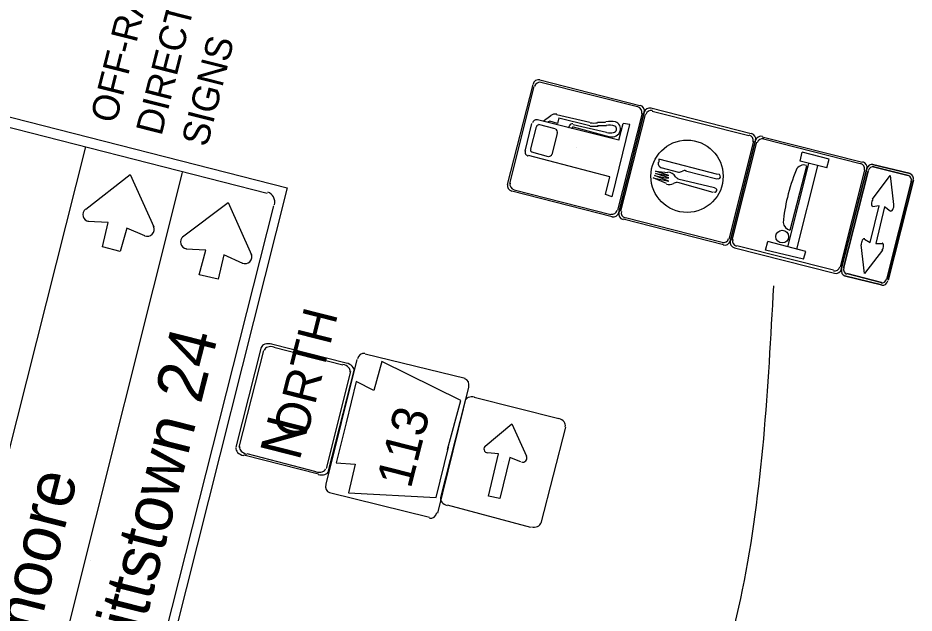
# Model space of a CAD drawing. Extents: x 644898 to 648326, y 298294 to 300670.
# Drawn here: x 647909.2 to 648009.9, y 300525.8 to 300592.6 of the extents above; entities that cross this region are included whole.
import ezdxf

# ---------------------------------------------------------------- set-up
doc = ezdxf.new("R2010")
doc.units = 0
doc.layers.add('2', color=7, linetype='Continuous')

msp = doc.modelspace()

# ---------------------------------------------------------------- linework, layer by layer
at = {"layer": '2'}
for p, q in [((647964.2, 300573.87), (647967.07, 300585.12)), ((647964.45, 300573.99), (647967.2, 300584.87)), ((647967.82, 300585.62), (647979.07, 300582.74)), ((647967.95, 300585.37), (647978.82, 300582.62)), ((647905.7, 300582.12), (647939.45, 300573.49)), ((647979.32, 300581.87), (647976.57, 300570.99)), ((647979.57, 300581.99), (647976.7, 300570.74)), ((647976.7, 300570.74), (647979.57, 300581.99)), ((647980.32, 300582.49), (647991.57, 300579.62)), ((647980.45, 300582.12), (647991.32, 300579.37)), ((647966.2, 300577.62), (647966.95, 300580.74)), ((647976.7, 300578.87), (647967.57, 300581.12)), ((647968.2, 300580.99), (647969.07, 300581.62)), ((647968.95, 300580.99), (647968.7, 300580.87)), ((647969.82, 300580.74), (647968.95, 300580.99)), ((647969.7, 300581.74), (647973.45, 300580.87)), ((647969.95, 300581.37), (647969.82, 300580.74)), ((647969.95, 300581.37), (647973.45, 300580.49)), ((647974.32, 300580.87), (647975.2, 300580.87)), ((647976.7, 300578.87), (647977.2, 300580.74)), ((647976.95, 300570.87), (647979.7, 300581.74)), ((647977.95, 300580.62), (647977.2, 300580.74)), ((647937.2, 300572.87), (647907.32, 300580.49)), ((647966.82, 300577.87), (647967.45, 300580.37)), ((647969.57, 300580.12), (647967.7, 300580.62)), ((647971.07, 300580.24), (647971.2, 300580.49)), ((647971.45, 300580.12), (647971.45, 300580.24)), ((647971.57, 300580.62), (647975.32, 300579.74)), ((647971.57, 300580.37), (647975.7, 300579.24)), ((647974.32, 300580.49), (647975.32, 300580.49)), ((647975.95, 300572.49), (647977.95, 300580.62)), ((647969.2, 300577.24), (647969.82, 300579.62)), ((647991.82, 300578.74), (647989.07, 300567.74)), ((647992.07, 300578.87), (647989.2, 300567.49)), ((647989.2, 300567.49), (647992.07, 300578.87)), ((647992.82, 300579.24), (648004.07, 300576.37)), ((647992.95, 300578.99), (648003.82, 300576.24)), ((647898.32, 300504.87), (647916.82, 300578.12)), ((647971.95, 300577.99), (647971.95, 300577.99)), ((647989.45, 300567.62), (647992.2, 300578.62)), ((647975.7, 300574.74), (647966.57, 300577.12)), ((647968.82, 300576.99), (647966.95, 300577.49)), ((647987.82, 300574.99), (647981.2, 300576.74)), ((647981.2, 300576.74), (647981.2, 300576.37)), ((647997.07, 300576.49), (647997.32, 300577.49)), ((648000.32, 300576.74), (647997.32, 300577.49)), ((648000.07, 300575.74), (648000.32, 300576.74)), ((647983.45, 300575.24), (647981.45, 300575.74)), ((647995.7, 300566.87), (647998.07, 300576.24)), ((647995.95, 300568.74), (647997.82, 300575.99)), ((647996.7, 300566.62), (647999.07, 300575.99)), ((648000.07, 300575.74), (647997.07, 300576.49)), ((648005.2, 300576.12), (648009.45, 300575.12)), ((648009.45, 300575.12), (648005.2, 300576.12)), ((648005.32, 300575.87), (648009.2, 300574.87)), ((648009.2, 300574.87), (648005.32, 300575.87)), ((647909.32, 300502.12), (647927.7, 300575.24)), ((647916.82, 300571.12), (647921.82, 300574.99)), ((647921.82, 300574.99), (647924.45, 300569.12)), ((647975.2, 300572.74), (647975.7, 300574.74)), ((647982.32, 300574.24), (647980.7, 300574.87)), ((647980.7, 300574.87), (647981.95, 300574.62)), ((647980.82, 300575.37), (647982.2, 300575.24)), ((647982.32, 300574.87), (647980.82, 300575.37)), ((647982.32, 300574.62), (647980.82, 300575.12)), ((647980.82, 300575.12), (647982.32, 300574.87)), ((647987.7, 300574.49), (647984.2, 300575.37)), ((647984.45, 300574.74), (647984.45, 300574.74)), ((648004.32, 300575.49), (648001.57, 300564.62)), ((648004.57, 300575.62), (648001.7, 300564.37)), ((648001.7, 300564.37), (648004.57, 300575.62)), ((648004.57, 300575.62), (648001.7, 300564.37)), ((648001.95, 300564.49), (648004.7, 300575.37)), ((648004.7, 300575.37), (648001.95, 300564.49)), ((648005.2, 300572.24), (648007.2, 300574.87)), ((648007.2, 300574.87), (648007.57, 300571.62)), ((647982.07, 300573.99), (647980.57, 300574.62)), ((647980.57, 300574.62), (647982.32, 300574.24)), ((647981.95, 300574.62), (647982.32, 300574.62)), ((647987.45, 300573.49), (647983.32, 300574.49)), ((647987.32, 300572.99), (647983.32, 300574.12)), ((648009.57, 300574.24), (648006.82, 300563.24)), ((648006.82, 300563.24), (648009.57, 300574.24)), ((648009.82, 300574.37), (648006.95, 300563.12)), ((648006.95, 300563.12), (648009.82, 300574.37)), ((647939.45, 300573.49), (647920.45, 300498.24)), ((647975.95, 300570.24), (647964.7, 300573.12)), ((647975.82, 300570.49), (647964.95, 300573.24)), ((647975.95, 300572.49), (647975.2, 300572.74)), ((647927.7, 300567.99), (647932.82, 300571.87)), ((647932.82, 300571.87), (647935.45, 300565.99)), ((647919.95, 300500.49), (647937.95, 300571.49)), ((647996.95, 300571.62), (647996.95, 300571.62)), ((648004.95, 300567.37), (648005.95, 300571.49)), ((648004.95, 300567.37), (648005.95, 300571.49)), ((648005.95, 300571.49), (648005.2, 300571.37)), ((648006.57, 300571.37), (648005.57, 300567.24)), ((648006.57, 300571.37), (648005.57, 300567.24)), ((648007.2, 300570.87), (648006.57, 300571.37)), ((647919.32, 300569.62), (647917.07, 300569.74)), ((647988.45, 300567.12), (647977.2, 300569.99)), ((647988.32, 300567.37), (647977.45, 300570.12)), ((647918.7, 300566.87), (647919.32, 300569.62)), ((647921.45, 300568.99), (647920.7, 300566.37)), ((647923.45, 300568.12), (647921.45, 300568.99)), ((648005.7, 300569.37), (648005.7, 300569.37)), ((648005.7, 300569.37), (648005.7, 300569.37)), ((648005.7, 300569.37), (648005.7, 300569.37)), ((648005.7, 300569.37), (648005.7, 300569.37)), ((648004.32, 300567.74), (648004.95, 300567.37)), ((647920.7, 300566.37), (647918.7, 300566.87)), ((648000.95, 300563.87), (647989.7, 300566.74)), ((648000.82, 300564.24), (647989.95, 300566.99)), ((647993.2, 300566.49), (647993.45, 300567.49)), ((647997.7, 300566.37), (647993.45, 300567.49)), ((648004.32, 300563.87), (648003.95, 300567.12)), ((648005.57, 300567.24), (648006.32, 300567.24)), ((647930.32, 300566.49), (647928.07, 300566.62)), ((647929.57, 300563.74), (647930.32, 300566.49)), ((647932.32, 300565.99), (647931.7, 300563.24)), ((647934.45, 300564.99), (647932.32, 300565.99)), ((647997.45, 300565.49), (647993.2, 300566.49)), ((647997.45, 300565.49), (647997.7, 300566.37)), ((648006.32, 300566.49), (648004.32, 300563.87)), ((647931.7, 300563.24), (647929.57, 300563.74)), ((648006.2, 300562.87), (648002.32, 300563.87)), ((648002.32, 300563.87), (648006.2, 300562.87)), ((648006.2, 300562.62), (648002.07, 300563.62)), ((648002.07, 300563.62), (648006.2, 300562.62)), ((647933.7, 300544.37), (647936.57, 300555.62)), ((647937.7, 300555.99), (647946.07, 300553.87)), ((647937.95, 300555.62), (647945.7, 300553.62)), ((647934.07, 300544.37), (647936.82, 300555.24)), ((647948.2, 300554.87), (647959.45, 300552.12)), ((647943.82, 300540.24), (647947.32, 300554.24)), ((647950.07, 300553.99), (647949.2, 300550.74)), ((647958.95, 300549.62), (647950.07, 300553.99)), ((647946.57, 300552.87), (647943.82, 300541.99)), ((647946.95, 300552.99), (647944.07, 300541.74)), ((647947.2, 300551.74), (647946.07, 300547.12)), ((647949.2, 300550.74), (647947.2, 300551.74)), ((647959.82, 300551.12), (647956.32, 300536.99)), ((647957.45, 300544.12), (647958.95, 300549.62)), ((647960.45, 300549.99), (647969.95, 300547.62)), ((647960.45, 300549.99), (647969.95, 300547.62)), ((647960.45, 300549.99), (647969.95, 300547.62)), ((647940.32, 300548.62), (647940.32, 300548.62)), ((647956.7, 300538.74), (647959.45, 300549.49)), ((647956.7, 300538.74), (647959.45, 300549.49)), ((647956.7, 300538.74), (647959.45, 300549.49)), ((647946.07, 300547.12), (647944.95, 300542.62)), ((647961.7, 300544.49), (647964.7, 300546.99)), ((647964.7, 300546.99), (647966.32, 300543.37)), ((647970.7, 300546.62), (647967.95, 300535.87)), ((647970.7, 300546.62), (647967.95, 300535.87)), ((647970.7, 300546.62), (647967.95, 300535.87)), ((647942.95, 300541.37), (647934.57, 300543.49)), ((647942.7, 300541.62), (647934.95, 300543.62)), ((647956.2, 300538.74), (647957.57, 300544.37)), ((647963.2, 300543.62), (647961.95, 300543.74)), ((647962.07, 300538.87), (647963.2, 300543.62)), ((647944.95, 300542.62), (647947.07, 300542.49)), ((647947.07, 300542.49), (647946.32, 300539.24)), ((647964.45, 300543.24), (647963.32, 300538.62)), ((647963.7, 300542.74), (647963.7, 300542.74)), ((647963.7, 300542.74), (647963.7, 300542.74)), ((647963.7, 300542.74), (647963.7, 300542.74)), ((647965.7, 300542.74), (647964.45, 300543.24)), ((647955.45, 300536.49), (647944.2, 300539.24)), ((647946.32, 300539.24), (647956.2, 300538.74)), ((647963.32, 300538.62), (647962.07, 300538.87)), ((647966.82, 300535.37), (647957.45, 300537.87)), ((647966.82, 300535.37), (647957.45, 300537.87)), ((647966.82, 300535.37), (647957.45, 300537.87)), ((647955.45, 300536.49), (647955.45, 300536.49)), ((647917.45, 300534.49), (647917.45, 300534.49)), ((647917.45, 300534.49), (647917.45, 300534.49)), ((647917.32, 300531.62), (647917.32, 300531.62)), ((647928.2, 300528.87), (647928.2, 300528.87)), ((647928.2, 300528.87), (647928.2, 300528.87))]:
    msp.add_line(p, q, dxfattribs=at)
for centre, radius in [((647984.37, 300574.8), 4.06), ((647995.06, 300568.03), 0.717)]:
    msp.add_circle(centre, radius, dxfattribs=at)
for centre, radius, start, end in [((647967.69, 300584.99), 0.645, 75.7754, 165.7754), ((647967.83, 300584.76), 0.597, 75.7754, 165.7754), ((647978.94, 300582.14), 0.645, 345.7754, 75.7754), ((647969.59, 300580.79), 0.991, 81.3158, 122.9841), ((647978.71, 300582), 0.597, 345.7754, 75.7754), ((647980.19, 300581.82), 0.645, 75.7754, 165.7754), ((647980.33, 300581.59), 0.597, 75.7754, 165.7754), ((647967.47, 300580.67), 0.486, 83.6778, 164.7031), ((647973.9, 300583.76), 2.98, 262.3862, 278.0519), ((647975.78, 300578.28), 2.68, 78.1727, 101.1253), ((647976.06, 300580.11), 0.84, 344.9893, 71.1198), ((647967.71, 300580.3), 0.274, 92.8615, 169.1523), ((647969.41, 300579.75), 0.392, 341.4902, 59.3145), ((647971.46, 300580.37), 0.318, 75.201, 153.6335), ((647971.54, 300580.24), 0.0771, 64.9719, 167.615), ((647973.9, 300583.76), 3.35, 262.3862, 278.0519), ((647975.67, 300578.96), 1.59, 68.02, 103.4387), ((647975.96, 300580.18), 0.953, 254.9902, 342.4176), ((647976.07, 300580.11), 0.381, 275.7441, 58.872), ((647975.71, 300581.2), 1.53, 256.8807, 285.2561), ((647991.22, 300578.83), 0.597, 345.7754, 75.7754), ((647991.45, 300578.97), 0.645, 345.7754, 75.7754), ((647992.7, 300578.65), 0.645, 75.7754, 165.7754), ((647992.84, 300578.42), 0.597, 75.7754, 165.7754), ((647967.03, 300577.75), 0.249, 154.0614, 244.0323), ((647966.59, 300577.5), 0.415, 157.4008, 262.3628), ((647968.88, 300577.35), 0.314, 262.0164, 342.4308), ((647981.63, 300576.25), 0.507, 165.7754, 255.7754), ((647997.47, 300575.18), 0.888, 69.9409, 158.7047), ((648003.72, 300575.66), 0.597, 345.7754, 75.7754), ((648003.95, 300575.8), 0.645, 345.7754, 75.7754), ((647982.21, 300574.25), 0.996, 30.4773, 89.3124), ((647983.51, 300575.01), 0.504, 210.7055, 255.4294), ((647983.44, 300576.11), 0.835, 266.9017, 299.9124), ((647984.1, 300575.01), 0.443, 68.9162, 122.8856), ((647987.86, 300574.78), 0.261, 247.2807, 84.2701), ((648013.8, 300568.22), 18.64, 157.0049, 166.9537), ((647964.84, 300573.74), 0.645, 165.7754, 255.7754), ((647965.07, 300573.88), 0.597, 165.7754, 255.7754), ((647982.41, 300574.73), 0.869, 247.3155, 299.7154), ((647983.18, 300573.5), 0.593, 81.6072, 125.4072), ((647987.48, 300573.25), 0.234, 244.4009, 87.1499), ((648017.53, 300567.22), 22.5, 166.6162, 173.9535), ((647917.23, 300570.5), 0.745, 125.638, 266.3035), ((647975.95, 300571.12), 0.597, 255.7754, 345.7754), ((647976.09, 300570.88), 0.645, 255.7754, 345.7754), ((647977.34, 300570.57), 0.645, 165.7754, 255.7754), ((647977.57, 300570.71), 0.597, 165.7754, 255.7754), ((647923.76, 300568.8), 0.745, 244.0264, 27.9331), ((647996.19, 300569.75), 1.04, 188.6173, 255.6836), ((647928.2, 300567.43), 0.745, 125.638, 266.3035), ((647988.46, 300567.95), 0.597, 255.7754, 345.7754), ((647990.08, 300567.54), 0.597, 165.7754, 255.7754), ((647988.6, 300567.71), 0.645, 255.7754, 345.7754), ((647989.85, 300567.4), 0.645, 165.7754, 255.7754), ((647934.73, 300565.73), 0.745, 244.0264, 27.9331), ((648000.96, 300564.78), 0.597, 255.7754, 345.7754), ((648001.1, 300564.54), 0.645, 255.7754, 345.7754), ((647962, 300544.19), 0.45, 126.1169, 265.3481), ((647965.93, 300543.16), 0.45, 247.2918, 24.1455)]:
    msp.add_arc(centre, radius, start, end, dxfattribs=at)
for centre, major_axis, ratio, start_param, end_param in [((648005.1, 300575.51), (-0.158, -0.625), 0.833333, 3.141593, 4.712389), ((648005.1, 300575.51), (0.158, 0.625), 0.833333, 0, 1.570796), ((648005.21, 300575.28), (-0.147, -0.578), 0.833333, 3.141593, 4.712389), ((648005.21, 300575.28), (0.147, 0.578), 0.833333, 0, 1.570796), ((648009.07, 300574.31), (0.147, 0.578), 0.833333, 4.712389, 6.283185), ((648009.07, 300574.31), (0.147, 0.578), 0.833333, 4.712389, 6.283185), ((648009.27, 300574.45), (0.158, 0.625), 0.833333, 4.712389, 6.283185), ((648009.27, 300574.45), (0.158, 0.625), 0.833333, 4.712389, 6.283185), ((647936.98, 300571.84), (0.29, 1.16), 0.890186, 4.712389, 6.283185), ((648005.33, 300571.87), (-0.113, -0.446), 0.5, 4.011799, 6.466875), ((648007.35, 300571.34), (-0.113, -0.446), 0.5, 6.078068, 8.589712), ((648004.19, 300567.34), (0.113, 0.446), 0.5, 6.099495, 8.554572), ((648006.21, 300566.85), (0.113, 0.446), 0.5, 3.976659, 6.488303), ((648002.25, 300564.25), (-0.158, -0.625), 0.833333, 4.712389, 6.283185), ((648002.25, 300564.25), (-0.158, -0.625), 0.833333, 4.712389, 6.283185), ((648002.45, 300564.4), (-0.147, -0.578), 0.833333, 4.712389, 6.283185), ((648002.45, 300564.4), (-0.147, -0.578), 0.833333, 4.712389, 6.283185), ((648006.31, 300563.42), (0.147, 0.578), 0.833333, 3.141593, 4.712389), ((648006.31, 300563.42), (-0.147, -0.578), 0.833333, 0, 1.570796), ((648006.41, 300563.2), (0.158, 0.625), 0.833333, 3.141593, 4.712389), ((648006.41, 300563.2), (-0.158, -0.625), 0.833333, 0, 1.570796), ((647937.58, 300555.32), (-1.04, 0.26), 0.6, 4.712389, 6.283185), ((647937.84, 300555.05), (-0.964, 0.244), 0.6, 4.712389, 6.283185), ((647947.96, 300554.13), (-0.198, -0.782), 0.8, 3.141593, 4.712389), ((647945.56, 300553.1), (-0.964, 0.244), 0.6, 3.141593, 4.712389), ((647945.92, 300553.21), (-1.04, 0.26), 0.6, 3.141593, 4.712389), ((647959.22, 300551.28), (0.198, 0.782), 0.8, 4.712389, 6.283185), ((647960.31, 300549.3), (-0.903, 0.229), 0.769266, 4.712389, 6.283185), ((647960.31, 300549.3), (-0.903, 0.229), 0.769266, 4.712389, 6.283185), ((647960.31, 300549.3), (-0.903, 0.229), 0.769266, 4.712389, 6.283185), ((647969.79, 300546.9), (-0.903, 0.229), 0.769266, 3.141593, 4.712389), ((647969.79, 300546.9), (-0.903, 0.229), 0.769266, 3.141593, 4.712389), ((647969.79, 300546.9), (-0.903, 0.229), 0.769266, 3.141593, 4.712389), ((647934.73, 300544.06), (1.04, -0.26), 0.6, 3.141593, 4.712389), ((647935.08, 300544.17), (0.964, -0.244), 0.6, 3.141593, 4.712389), ((647942.8, 300542.21), (0.964, -0.244), 0.6, 4.712389, 6.283185), ((647943.07, 300541.95), (1.04, -0.26), 0.6, 4.712389, 6.283185), ((647944.4, 300540.07), (-0.198, -0.782), 0.8, 4.712389, 6.283185), ((647957.58, 300538.53), (0.903, -0.229), 0.769266, 3.141593, 4.712389), ((647957.58, 300538.53), (0.903, -0.229), 0.769266, 3.141593, 4.712389), ((647957.58, 300538.53), (0.903, -0.229), 0.769266, 3.141593, 4.712389), ((647955.65, 300537.21), (0.198, 0.782), 0.8, 3.141593, 4.712389), ((647967.06, 300536.13), (0.903, -0.229), 0.769266, 4.712389, 6.283185), ((647967.06, 300536.13), (0.903, -0.229), 0.769266, 4.712389, 6.283185), ((647967.06, 300536.13), (0.903, -0.229), 0.769266, 4.712389, 6.283185)]:
    msp.add_ellipse(centre, major_axis=major_axis, ratio=ratio, start_param=start_param, end_param=end_param, dxfattribs=at)
msp.add_spline([(647994.07, 300562.49), (647990.57, 300528.37), (647982.82, 300497.49), (647980.2, 300481.37), (647977.07, 300471.49), (647972.95, 300467.99), (647969.2, 300467.12), (647963.7, 300467.99)], degree=3, dxfattribs=at)

# ---------------------------------------------------------------- texts
for s, height, rotation, p in [('DIRECTIONAL', 3, 75.7789, (647925.32, 300579.24)), ('OFF-RAMP', 3, 75.7789, (647920.2, 300580.62)), ('SIGNS', 3, 75.7789, (647930.45, 300577.99)), ('ORTH', 3.875, 75.7783, (647941.57, 300545.12)), ('West Pittstown 24', 5.3752, 75.7788, (647917.57, 300501.12)), ('113', 4, 75.7777, (647953.32, 300539.62)), ('N', 4.63, 75.7284, (647940.82, 300542.74)), ('Glenmoore   ', 5.3752, 75.7788, (647907.22, 300506.62))]:
    msp.add_text(s, height=height, rotation=rotation, dxfattribs=at).set_placement(p)

doc.saveas('drawing.dxf')
